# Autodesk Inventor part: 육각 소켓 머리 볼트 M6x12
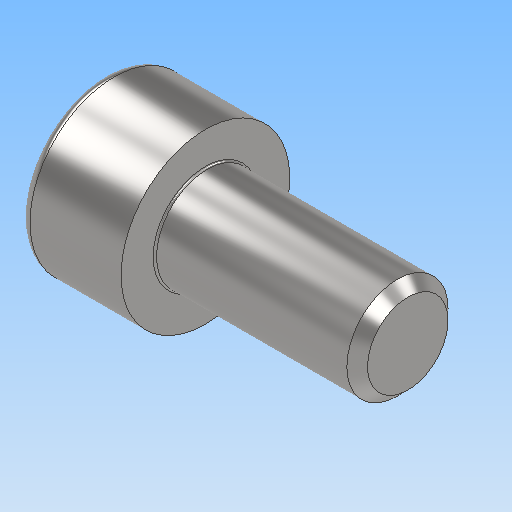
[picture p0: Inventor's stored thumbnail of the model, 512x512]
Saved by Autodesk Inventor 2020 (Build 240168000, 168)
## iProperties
Created: 2024-07
Part Number: 육각 소켓 머리 볼트 M6x12
Material: 강철, 연강
Description: 6각머리 태핑 나사
Document SubType Name: Modeling
Designer: oem
Density: 7.85 g/cm^3
Appearance: 기본값
Author: jhkim
Sending System: Autodesk Inventor 2025
Preprocessor: ST-DEVELOPER v20
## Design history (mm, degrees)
feature "Solid1"
node "솔리드1"
